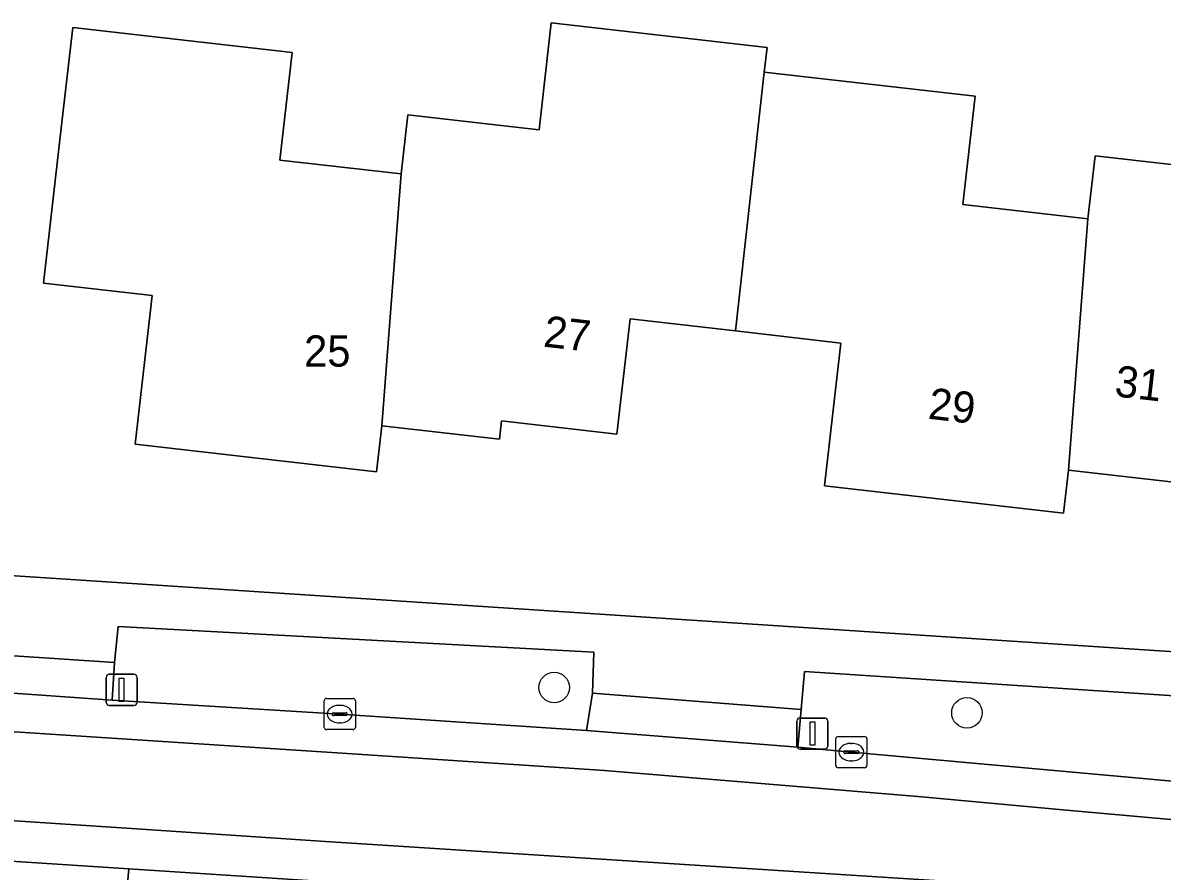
# Model space of a CAD drawing. Extents: x 162396 to 163643, y 386452 to 387406.
# Drawn here: x 162817.97 to 162854.51, y 386589.03 to 386616.22 of the extents above; entities that cross this region are included whole.
import ezdxf

# ---------------------------------------------------------------- set-up
doc = ezdxf.new("R2010")
doc.units = 0
for name, color, linetype in [('IMGEO_Boom', 7, 'Continuous'), ('IMGEO_Erf', 7, 'Continuous'), ('IMGEO_Groenvoorziening', 7, 'Continuous'), ('IMGEO_Kolk', 7, 'Continuous'), ('IMGEO_Lichtmast', 7, 'Continuous'), ('IMGEO_Pand', 7, 'Continuous'), ('IMGEO_Pand_nummerreeks', 7, 'Continuous'), ('IMGEO_Parkeervlak_open', 7, 'Continuous'), ('IMGEO_Rijbaan_lokaal_gesloten', 7, 'Continuous'), ('IMGEO_Rijbaan_lokaal_open', 7, 'Continuous'), ('IMGEO_Voetpad_open', 7, 'Continuous')]:
    doc.layers.add(name, color=color, linetype=linetype)

msp = doc.modelspace()

# ---------------------------------------------------------------- linework, layer by layer
at = {"layer": 'IMGEO_Boom'}
for centre in [(162835.01, 386594.914), (162848.244, 386594.102)]:
    msp.add_circle(centre, 0.489, dxfattribs=at)
at = {"layer": 'IMGEO_Erf'}
for points in [[(162855.255, 386601.454), (162851.5, 386601.882), (162851.342, 386600.498), (162843.675, 386601.374), (162844.198, 386605.956), (162840.822, 386606.342), (162837.445, 386606.728), (162837.023, 386603.035), (162833.322, 386603.458), (162833.256, 386602.873), (162829.481, 386603.304), (162829.313, 386601.829), (162821.575, 386602.709), (162822.12, 386607.477), (162818.636, 386607.875), (162819.204, 386612.843), (162819.573, 386616.073), (162826.605, 386615.27), (162826.211, 386611.822), (162830.099, 386611.378), (162830.316, 386613.273), (162834.527, 386612.792), (162834.918, 386616.221), (162841.838, 386615.431), (162841.748, 386614.64), (162848.506, 386613.868), (162848.109, 386610.399), (162852.124, 386609.94), (162852.354, 386611.956), (162856.491, 386611.483)], [(162793.321, 386600.105), (162796.177, 386599.905), (162874.812, 386594.75), (162878.183, 386594.518)]]:
    msp.add_lwpolyline(points, dxfattribs=at)
at = {"layer": 'IMGEO_Groenvoorziening'}
for points in [[(162820.916, 386595.714), (162820.841, 386594.51), (162828.135, 386594.063), (162836.05, 386593.531), (162836.234, 386594.736), (162836.278, 386596.048), (162821.025, 386596.875)], [(162843.035, 386595.429), (162842.934, 386594.204), (162842.82, 386593.006), (162844.539, 386592.844), (162857.433, 386591.68), (162857.528, 386592.874), (162857.658, 386594.461)]]:
    msp.add_lwpolyline(points, close=True, dxfattribs=at)
at = {"layer": 'IMGEO_Kolk'}
for p, q in [((162827.634, 386593.637), (162827.634, 386594.489)), ((162827.709, 386594.563), (162828.561, 386594.563)), ((162828.635, 386594.489), (162828.635, 386593.637)), ((162827.893, 386594.057), (162827.893, 386594.069)), ((162828.331, 386594.02), (162827.933, 386594.02)), ((162827.936, 386594.106), (162828.334, 386594.106)), ((162828.122, 386594.343), (162828.147, 386594.343)), ((162828.377, 386594.069), (162828.377, 386594.057)), ((162828.145, 386593.783), (162828.12, 386593.783)), ((162828.561, 386593.563), (162827.709, 386593.563)), ((162844.113, 386593.344), (162844.965, 386593.344)), ((162844.038, 386592.418), (162844.038, 386593.27)), ((162844.526, 386593.124), (162844.551, 386593.124)), ((162845.039, 386593.27), (162845.039, 386592.418)), ((162844.297, 386592.838), (162844.297, 386592.85)), ((162844.735, 386592.801), (162844.337, 386592.801)), ((162844.34, 386592.887), (162844.738, 386592.887)), ((162844.549, 386592.564), (162844.524, 386592.564)), ((162844.781, 386592.85), (162844.781, 386592.838)), ((162844.965, 386592.344), (162844.113, 386592.344))]:
    msp.add_line(p, q, dxfattribs=at)
for points in [[(162827.634, 386593.637), (162827.634, 386594.489)], [(162827.709, 386594.563), (162828.561, 386594.563)], [(162828.635, 386594.489), (162828.635, 386593.637)], [(162828.561, 386593.563), (162827.709, 386593.563)], [(162844.113, 386593.344), (162844.965, 386593.344)], [(162844.038, 386592.418), (162844.038, 386593.27)], [(162845.039, 386593.27), (162845.039, 386592.418)], [(162844.965, 386592.344), (162844.113, 386592.344)]]:
    msp.add_lwpolyline(points, dxfattribs=at)
for centre, radius, start, end in [((162827.711, 386594.487), 0.0765, 91.552, 178.448), ((162827.711, 386594.487), 0.0765, 91.552, 178.448), ((162828.559, 386594.487), 0.0765, 1.552, 88.448), ((162828.559, 386594.487), 0.0765, 1.552, 88.448), ((162827.933, 386594.066), 0.0403, 85.8775, 175.7526), ((162827.93, 386594.056), 0.0366, 178.938, 274.7102), ((162828.334, 386594.063), 0.043, 264.8664, 352.4533), ((162828.338, 386594.068), 0.0386, 1.7309, 96.639), ((162827.711, 386593.639), 0.0765, 181.552, 268.448), ((162827.711, 386593.639), 0.0765, 181.552, 268.448), ((162828.559, 386593.639), 0.0765, 271.552, 358.448), ((162828.559, 386593.639), 0.0765, 271.552, 358.448), ((162844.115, 386593.268), 0.0765, 91.552, 178.448), ((162844.115, 386593.268), 0.0765, 91.552, 178.448), ((162844.963, 386593.268), 0.0765, 1.552, 88.448), ((162844.963, 386593.268), 0.0765, 1.552, 88.448), ((162844.337, 386592.847), 0.0403, 85.8775, 175.7526), ((162844.334, 386592.837), 0.0366, 178.938, 274.7102), ((162844.738, 386592.844), 0.043, 264.8664, 352.4533), ((162844.742, 386592.849), 0.0386, 1.7309, 96.639), ((162844.115, 386592.42), 0.0765, 181.552, 268.448), ((162844.115, 386592.42), 0.0765, 181.552, 268.448), ((162844.963, 386592.42), 0.0765, 271.552, 358.448), ((162844.963, 386592.42), 0.0765, 271.552, 358.448)]:
    msp.add_arc(centre, radius, start, end, dxfattribs=at)
for centre, major_axis, ratio, start_param, end_param in [((162828.121, 386594.063), (-0.387, 0.002), 0.722429, 4.712389, 7.853982), ((162828.146, 386594.063), (-0.39, 0.002), 0.717154, 1.570796, 4.712389), ((162844.525, 386592.844), (-0.387, 0.002), 0.722429, 4.712389, 7.853982), ((162844.55, 386592.844), (-0.39, 0.002), 0.717154, 1.570796, 4.712389)]:
    msp.add_ellipse(centre, major_axis=major_axis, ratio=ratio, start_param=start_param, end_param=end_param, dxfattribs=at)
at = {"layer": 'IMGEO_Lichtmast'}
for p, q in [((162820.646, 386594.439), (162820.646, 386595.239)), ((162820.646, 386595.239), (162820.646, 386594.439)), ((162820.746, 386595.339), (162821.536, 386595.339)), ((162821.536, 386595.339), (162820.746, 386595.339)), ((162821.636, 386595.239), (162821.636, 386594.439)), ((162821.636, 386594.439), (162821.636, 386595.239)), ((162821.536, 386594.339), (162820.746, 386594.339)), ((162820.746, 386594.339), (162821.536, 386594.339)), ((162842.793, 386593.036), (162842.793, 386593.836)), ((162842.793, 386593.836), (162842.793, 386593.036)), ((162842.893, 386593.936), (162843.683, 386593.936)), ((162843.683, 386593.936), (162842.893, 386593.936)), ((162843.783, 386593.836), (162843.783, 386593.036)), ((162843.783, 386593.036), (162843.783, 386593.836)), ((162843.683, 386592.936), (162842.893, 386592.936)), ((162842.893, 386592.936), (162843.683, 386592.936))]:
    msp.add_line(p, q, dxfattribs=at)
for points in [[(162821.066, 386595.214), (162821.216, 386595.214), (162821.216, 386594.464), (162821.066, 386594.464), (162821.066, 386595.214)], [(162843.213, 386593.811), (162843.363, 386593.811), (162843.363, 386593.061), (162843.213, 386593.061), (162843.213, 386593.811)]]:
    msp.add_lwpolyline(points, dxfattribs=at)
for centre, start, end in [((162820.746, 386595.239), 90, 180), ((162820.746, 386595.239), 90, 180), ((162821.536, 386595.239), 0, 90), ((162821.536, 386595.239), 360, 90), ((162820.746, 386594.439), 180, 270), ((162820.746, 386594.439), 180, 270), ((162821.536, 386594.439), 270, 0), ((162821.536, 386594.439), 270, 0), ((162842.893, 386593.836), 90, 180), ((162842.893, 386593.836), 90, 180), ((162843.683, 386593.836), 0, 90), ((162843.683, 386593.836), 360, 90), ((162842.893, 386593.036), 180, 270), ((162842.893, 386593.036), 180, 270), ((162843.683, 386593.036), 270, 0), ((162843.683, 386593.036), 270, 0)]:
    msp.add_arc(centre, 0.1, start, end, dxfattribs=at)
at = {"layer": 'IMGEO_Pand'}
for points in [[(162830.099, 386611.378), (162826.211, 386611.822), (162826.605, 386615.27), (162819.573, 386616.073), (162819.204, 386612.843), (162818.636, 386607.875), (162822.12, 386607.477), (162821.575, 386602.709), (162829.313, 386601.829), (162829.481, 386603.304)], [(162829.481, 386603.304), (162833.256, 386602.873), (162833.322, 386603.458), (162837.023, 386603.035), (162837.445, 386606.728), (162840.822, 386606.342), (162841.748, 386614.64), (162841.838, 386615.431), (162834.918, 386616.221), (162834.527, 386612.792), (162830.316, 386613.273), (162830.099, 386611.378)], [(162862.728, 386604.955), (162863.872, 386614.127), (162856.885, 386614.926), (162856.491, 386611.483), (162852.354, 386611.956), (162852.124, 386609.94), (162851.5, 386601.882), (162855.255, 386601.454), (162855.328, 386602.092), (162859.031, 386601.669), (162859.449, 386605.33)], [(162852.124, 386609.94), (162848.109, 386610.399), (162848.506, 386613.868), (162841.748, 386614.64), (162840.822, 386606.342), (162844.198, 386605.956), (162843.675, 386601.374), (162851.342, 386600.498), (162851.5, 386601.882)]]:
    msp.add_lwpolyline(points, close=True, dxfattribs=at)
at = {"layer": 'IMGEO_Parkeervlak_open'}
for points in [[(162821.37, 386589.103), (162821.202, 386587.174), (162827.484, 386586.769), (162844.212, 386585.667)], [(162845.666, 386587.525), (162821.37, 386589.103)]]:
    msp.add_lwpolyline(points, dxfattribs=at)
at = {"layer": 'IMGEO_Rijbaan_lokaal_gesloten'}
msp.add_lwpolyline([(162844.539, 386592.844), (162842.82, 386593.006), (162836.05, 386593.531), (162828.135, 386594.063), (162820.841, 386594.51), (162815.835, 386594.865), (162807.735, 386595.397), (162795.81, 386596.175), (162794.27, 386596.29), (162793.383, 386596.353), (162793.309, 386595.117), (162815.732, 386593.621), (162828.377, 386592.8), (162836.628, 386592.258), (162846.8, 386591.41), (162851.441, 386590.986), (162864.715, 386589.801), (162884.813, 386588.054), (162884.913, 386589.288), (162881.325, 386589.597), (162867.921, 386590.772), (162864.854, 386591.05), (162857.433, 386591.68)], close=True, dxfattribs=at)
for points in [[(162847.122, 386587.208), (162847.418, 386587.095), (162847.539, 386588.706), (162827.674, 386589.983), (162821.296, 386590.405), (162810.392, 386591.122), (162792.843, 386592.298)], [(162785.991, 386591.401), (162810.36, 386589.818), (162821.37, 386589.103), (162845.666, 386587.525)]]:
    msp.add_lwpolyline(points, dxfattribs=at)
at = {"layer": 'IMGEO_Rijbaan_lokaal_open'}
for points in [[(162777.205, 386597.414), (162777.106, 386596.182), (162742.964, 386598.357), (162729.614, 386599.202), (162729.422, 386596.356), (162742.035, 386595.583), (162758.459, 386594.528), (162779.404, 386593.181), (162792.843, 386592.298), (162810.392, 386591.122), (162821.296, 386590.405), (162827.674, 386589.983), (162847.539, 386588.706), (162847.418, 386587.095), (162847.502, 386587.063), (162848.895, 386586.285)], [(162862.955, 386585.795), (162863.046, 386587.104), (162884.585, 386585.214), (162884.813, 386588.054), (162864.715, 386589.801), (162851.441, 386590.986), (162846.8, 386591.41), (162836.628, 386592.258), (162828.377, 386592.8), (162815.732, 386593.621)]]:
    msp.add_lwpolyline(points, dxfattribs=at)
msp.add_lwpolyline([(162821.37, 386589.103), (162810.36, 386589.818), (162810.269, 386587.907), (162821.202, 386587.174)], close=True, dxfattribs=at)
at = {"layer": 'IMGEO_Voetpad_open'}
for points in [[(162878.183, 386594.518), (162874.812, 386594.75), (162796.177, 386599.905)], [(162793.383, 386596.353), (162794.27, 386596.29), (162795.81, 386596.175), (162795.992, 386598.493), (162815.975, 386597.198), (162815.902, 386596.049), (162820.916, 386595.714), (162821.025, 386596.875), (162836.278, 386596.048), (162836.234, 386594.736), (162842.934, 386594.204), (162843.035, 386595.429), (162857.658, 386594.461), (162857.528, 386592.874), (162864.943, 386592.226), (162865.081, 386593.973), (162886.151, 386592.618), (162886.437, 386597.323), (162885.026, 386598.614), (162885.003, 386598.636), (162884.974, 386598.604), (162883.647, 386597.143)]]:
    msp.add_lwpolyline(points, dxfattribs=at)
for points in [[(162820.916, 386595.714), (162815.902, 386596.049), (162815.835, 386594.865), (162820.841, 386594.51)], [(162842.934, 386594.204), (162836.234, 386594.736), (162836.05, 386593.531), (162842.82, 386593.006)]]:
    msp.add_lwpolyline(points, close=True, dxfattribs=at)

# ---------------------------------------------------------------- texts
at = {"layer": 'IMGEO_Pand_nummerreeks'}
for s, rotation, p in [('27', 353.4798, (162834.638, 386605.844)), ('31', 353.4974, (162852.954, 386604.252)), ('29', 353.4819, (162846.974, 386603.533))]:
    msp.add_text(s, height=1, rotation=rotation, dxfattribs=at).set_placement(p)
msp.add_text('25', height=1, dxfattribs=at).set_placement((162826.992, 386605.201))

doc.saveas('drawing.dxf')
